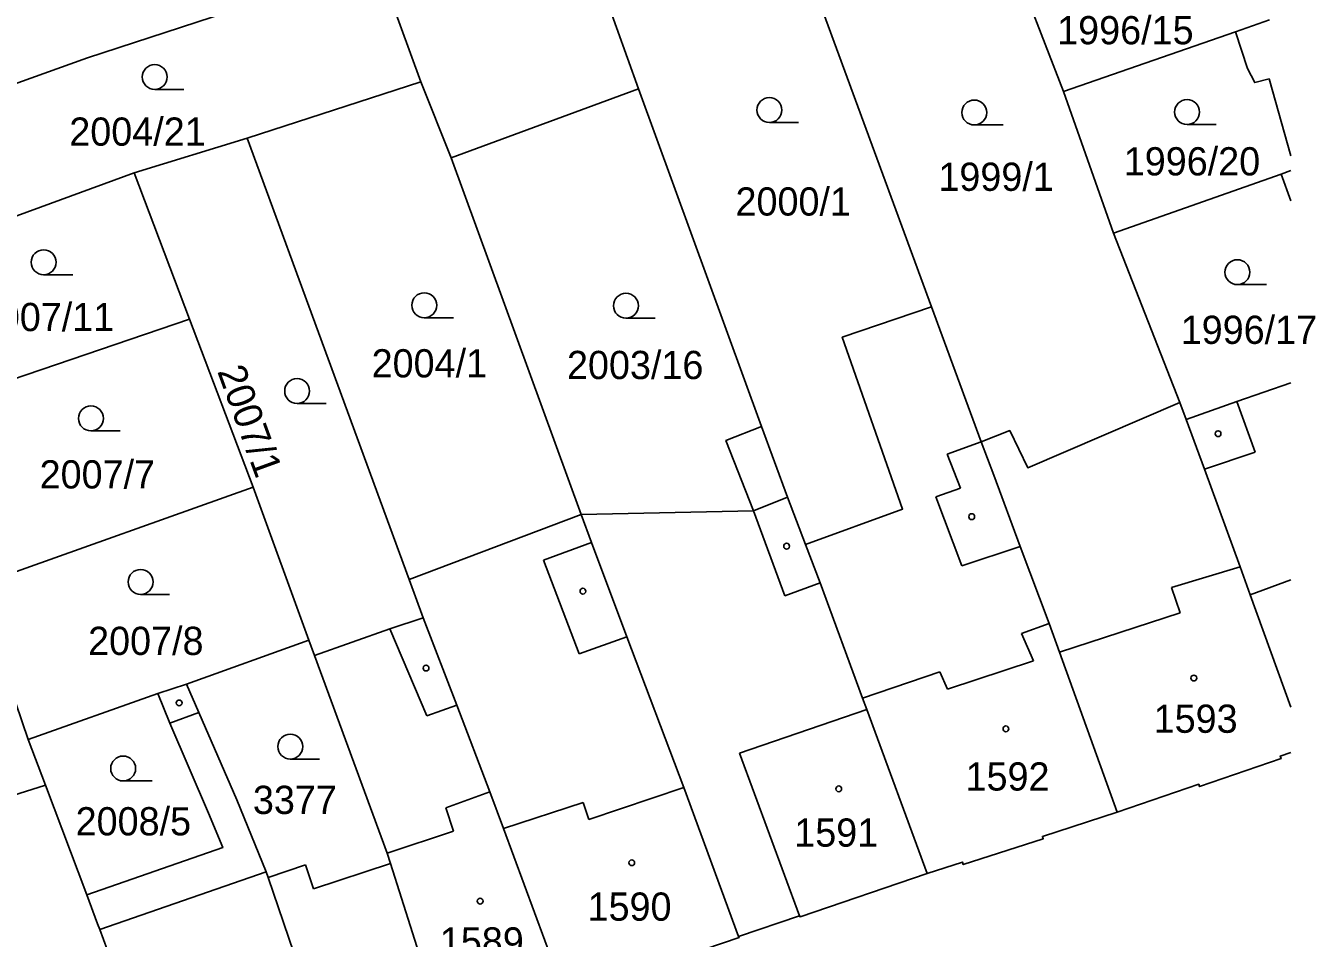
# Model space of a CAD drawing. Extents: x -564952 to -564307, y -1202373 to -1201847.
# Drawn here: x -564390.9 to -564313.2, y -1202270.6 to -1202215.7 of the extents above; entities that cross this region are included whole.
import ezdxf

# ---------------------------------------------------------------- set-up
doc = ezdxf.new("R2010")
doc.units = 0
for name, color, linetype in [('Hranice parcel', 7, 'Continuous'), ('Parcelní čísla', 7, 'Continuous'), ('Vnitřní kresba', 7, 'Continuous'), ('Značky budov', 7, 'Continuous'), ('Značky kultur', 7, 'Continuous')]:
    doc.layers.add(name, color=color, linetype=linetype)

msp = doc.modelspace()

# ---------------------------------------------------------------- linework, layer by layer
at = {"layer": 'Hranice parcel'}
for p, q in [((-564328.35, -1202219.63), (-564332.79, -1202208.17)), ((-564344.92, -1202209.13), (-564336.29, -1202232.6)), ((-564353.94, -1202219.47), (-564357.27, -1202210.21)), ((-564369.66, -1202211.88), (-564387.14, -1202217.59)), ((-564369.66, -1202211.88), (-564367.06, -1202219.05)), ((-564317.98, -1202216.02), (-564315.93, -1202215.31)), ((-564317.98, -1202216.02), (-564328.35, -1202219.63)), ((-564387.14, -1202217.59), (-564392.13, -1202219.38)), ((-564377.53, -1202222.44), (-564367.06, -1202219.05)), ((-564367.06, -1202219.05), (-564365.23, -1202223.62)), ((-564365.23, -1202223.62), (-564353.94, -1202219.47)), ((-564353.94, -1202219.47), (-564346.53, -1202239.8)), ((-564314.648, -1202223.506), (-564315.96, -1202218.87)), ((-564328.35, -1202219.63), (-564325.34, -1202228.16)), ((-564384.33, -1202224.53), (-564377.53, -1202222.44)), ((-564377.53, -1202222.44), (-564367.77, -1202249.02)), ((-564365.23, -1202223.62), (-564357.4, -1202245.11)), ((-564393.72, -1202227.96), (-564384.33, -1202224.53)), ((-564384.33, -1202224.53), (-564381, -1202233.34)), ((-564315.23, -1202224.6), (-564325.34, -1202228.16)), ((-564315.23, -1202224.6), (-564314.648, -1202224.392)), ((-564314.648, -1202226.212), (-564315.23, -1202224.6)), ((-564325.34, -1202228.16), (-564321.35, -1202238.36)), ((-564336.29, -1202232.6), (-564333.3, -1202240.74)), ((-564381, -1202233.34), (-564398.34, -1202239.24)), ((-564377.17, -1202243.46), (-564381, -1202233.34)), ((-564321.35, -1202238.36), (-564320.95, -1202239.38)), ((-564393.89, -1202249.42), (-564377.17, -1202243.46)), ((-564377.17, -1202243.46), (-564373.81, -1202252.67)), ((-564357.4, -1202245.11), (-564367.77, -1202249.02)), ((-564367.77, -1202249.02), (-564366.92, -1202251.33)), ((-564373.81, -1202252.67), (-564381.17, -1202255.32)), ((-564373.47, -1202253.61), (-564373.81, -1202252.67)), ((-564369.09, -1202265.51), (-564373.47, -1202253.61)), ((-564382.9, -1202255.9), (-564390.71, -1202258.66)), ((-564382.9, -1202255.9), (-564381.17, -1202255.32)), ((-564390.71, -1202258.66), (-564389.67, -1202261.41)), ((-564389.67, -1202261.41), (-564387.18, -1202268.03)), ((-564373.53, -1202267.65), (-564368.89, -1202266.13)), ((-564368.89, -1202266.13), (-564369.09, -1202265.51)), ((-564368.89, -1202266.13), (-564365.56, -1202276.57)), ((-564376.37, -1202266.64), (-564376.25, -1202266.98)), ((-564376.25, -1202266.98), (-564374.01, -1202266.22)), ((-564374.01, -1202266.22), (-564373.53, -1202267.65)), ((-564372.23, -1202278.84), (-564376.25, -1202266.98))]:
    msp.add_line(p, q, dxfattribs=at)
for points in [[(-564315.96, -1202218.87), (-564316.83, -1202219.09), (-564317.27, -1202218.23), (-564317.98, -1202216.02)], [(-564336.29, -1202232.6), (-564341.68, -1202234.43), (-564338.04, -1202244.78), (-564343.89, -1202246.92)], [(-564320.95, -1202239.38), (-564317.9, -1202238.31), (-564314.648, -1202237.168)], [(-564333.3, -1202240.74), (-564331.59, -1202240.05), (-564330.5, -1202242.29), (-564321.35, -1202238.36)], [(-564314.648, -1202256.715), (-564317.1, -1202249.94), (-564317.71, -1202248.27), (-564319.86, -1202242.37), (-564320.95, -1202239.38)], [(-564346.53, -1202239.8), (-564348.68, -1202240.65), (-564347.02, -1202244.89), (-564357.4, -1202245.11)], [(-564343.89, -1202246.92), (-564344.98, -1202244.07), (-564346.53, -1202239.8)], [(-564329.22, -1202251.67), (-564330.95, -1202247.03), (-564332.55, -1202242.74), (-564333.3, -1202240.74)], [(-564347.92, -1202270.53), (-564351.22, -1202261.56), (-564354.66, -1202252.48), (-564356.78, -1202246.8), (-564357.4, -1202245.11)], [(-564340.45, -1202256.18), (-564343.01, -1202249.22), (-564343.89, -1202246.92)], [(-564390.71, -1202258.66), (-564393.01, -1202251.97), (-564393.89, -1202249.42)], [(-564366.92, -1202251.33), (-564368.92, -1202251.99), (-564373.47, -1202253.61)], [(-564362.9, -1202261.82), (-564364.89, -1202256.6), (-564366.92, -1202251.33)], [(-564325.12, -1202263.05), (-564328.59, -1202253.41), (-564329.22, -1202251.67)], [(-564379.86, -1202263.1), (-564382.18, -1202257.68), (-564382.9, -1202255.9)], [(-564381.17, -1202255.32), (-564380.43, -1202257.03), (-564378.15, -1202262.3), (-564376.37, -1202266.64)], [(-564336.57, -1202266.74), (-564340.2, -1202256.86), (-564340.45, -1202256.18)], [(-564325.12, -1202263.05), (-564320.2, -1202261.36), (-564320.15, -1202261.5), (-564315.24, -1202259.81), (-564315.29, -1202259.66), (-564314.648, -1202259.44)], [(-564404.81, -1202265.7), (-564394.96, -1202262.25), (-564393.63, -1202262.65), (-564389.67, -1202261.41)], [(-564358.34, -1202274.15), (-564362.08, -1202264.03), (-564362.9, -1202261.82)], [(-564336.57, -1202266.74), (-564334.44, -1202266.05), (-564334.39, -1202266.2), (-564329.57, -1202264.64), (-564329.62, -1202264.5), (-564325.12, -1202263.05)], [(-564387.18, -1202268.03), (-564378.99, -1202265.17), (-564379.86, -1202263.1)], [(-564347.92, -1202270.53), (-564344.25, -1202269.28), (-564344.22, -1202269.35), (-564336.57, -1202266.74)], [(-564385.95, -1202271.31), (-564386.4, -1202270.12), (-564386.53, -1202269.77), (-564387.18, -1202268.03)], [(-564358.34, -1202274.15), (-564347.89, -1202270.6), (-564347.92, -1202270.53)]]:
    msp.add_lwpolyline(points, dxfattribs=at)
at = {"layer": 'Vnitřní kresba'}
for p, q in [((-564317.9, -1202238.31), (-564316.81, -1202241.36)), ((-564333.3, -1202240.74), (-564335.35, -1202241.47)), ((-564334.56, -1202243.53), (-564335.35, -1202241.47)), ((-564319.86, -1202242.37), (-564316.81, -1202241.36)), ((-564336.03, -1202244.05), (-564334.56, -1202243.53)), ((-564347.02, -1202244.89), (-564344.98, -1202244.07)), ((-564334.48, -1202248.21), (-564336.03, -1202244.05)), ((-564345.13, -1202250.01), (-564347.02, -1202244.89)), ((-564359.68, -1202247.86), (-564356.78, -1202246.8)), ((-564330.95, -1202247.03), (-564334.48, -1202248.21)), ((-564357.52, -1202253.5), (-564359.68, -1202247.86)), ((-564317.71, -1202248.27), (-564321.84, -1202249.51)), ((-564317.1, -1202249.94), (-564314.648, -1202249.043)), ((-564345.13, -1202250.01), (-564343.01, -1202249.22)), ((-564321.84, -1202249.51), (-564321.32, -1202251.03)), ((-564321.32, -1202251.03), (-564328.59, -1202253.41)), ((-564368.92, -1202251.99), (-564366.7, -1202257.24)), ((-564329.22, -1202251.67), (-564330.87, -1202252.28)), ((-564354.66, -1202252.48), (-564357.52, -1202253.5)), ((-564330.87, -1202252.28), (-564330.15, -1202253.92)), ((-564330.15, -1202253.92), (-564335.34, -1202255.63)), ((-564340.45, -1202256.18), (-564335.8, -1202254.59)), ((-564335.8, -1202254.59), (-564335.34, -1202255.63)), ((-564366.7, -1202257.24), (-564364.89, -1202256.6)), ((-564382.18, -1202257.68), (-564380.43, -1202257.03)), ((-564347.87, -1202259.48), (-564340.2, -1202256.86)), ((-564344.25, -1202269.28), (-564347.87, -1202259.48)), ((-564365.56, -1202262.79), (-564362.9, -1202261.82)), ((-564351.22, -1202261.56), (-564356.94, -1202263.49)), ((-564365.1, -1202264.19), (-564365.56, -1202262.79)), ((-564357.29, -1202262.46), (-564362.08, -1202264.03)), ((-564356.94, -1202263.49), (-564357.29, -1202262.46)), ((-564369.09, -1202265.51), (-564365.1, -1202264.19)), ((-564386.4, -1202270.12), (-564376.37, -1202266.64))]:
    msp.add_line(p, q, dxfattribs=at)
at = {"layer": 'Značky budov'}
for centre in [(-564319.037, -1202240.239), (-564333.877, -1202245.239), (-564345.027, -1202247.019), (-564357.297, -1202249.729), (-564366.747, -1202254.359), (-564320.497, -1202254.959), (-564381.617, -1202256.459), (-564331.817, -1202258.019), (-564341.887, -1202261.639), (-564354.357, -1202266.089), (-564363.487, -1202268.399)]:
    msp.add_circle(centre, 0.175, dxfattribs=at)
at = {"layer": 'Značky kultur'}
for p, q in [((-564383.093, -1202219.5), (-564381.343, -1202219.5)), ((-564346.063, -1202221.49), (-564344.313, -1202221.49)), ((-564333.723, -1202221.64), (-564331.973, -1202221.64)), ((-564320.903, -1202221.61), (-564319.153, -1202221.61)), ((-564389.783, -1202230.66), (-564388.033, -1202230.66)), ((-564317.873, -1202231.26), (-564316.123, -1202231.26)), ((-564366.853, -1202233.25), (-564365.103, -1202233.25)), ((-564354.703, -1202233.28), (-564352.953, -1202233.28)), ((-564374.513, -1202238.42), (-564372.763, -1202238.42)), ((-564386.933, -1202240.07), (-564385.183, -1202240.07)), ((-564383.943, -1202249.92), (-564382.193, -1202249.92)), ((-564374.923, -1202259.84), (-564373.173, -1202259.84)), ((-564384.993, -1202261.16), (-564383.243, -1202261.16))]:
    msp.add_line(p, q, dxfattribs=at)
for centre in [(-564383.093, -1202218.75), (-564346.063, -1202220.74), (-564333.723, -1202220.89), (-564320.903, -1202220.86), (-564389.783, -1202229.91), (-564317.873, -1202230.51), (-564366.853, -1202232.5), (-564354.703, -1202232.53), (-564374.513, -1202237.67), (-564386.933, -1202239.32), (-564383.943, -1202249.17), (-564374.923, -1202259.09), (-564384.993, -1202260.41)]:
    msp.add_circle(centre, 0.75, dxfattribs=at)

# ---------------------------------------------------------------- texts
at = {"layer": 'Parcelní čísla'}
for s, p in [('1996/15', (-564328.728, -1202216.78)), ('2004/21', (-564388.238, -1202222.89)), ('1996/20', (-564324.718, -1202224.68)), ('1999/1', (-564335.885, -1202225.61)), ('2000/1', (-564348.105, -1202227.1)), ('2007/11', (-564393.748, -1202234.06)), ('1996/17', (-564321.288, -1202234.83)), ('2004/1', (-564370.025, -1202236.85)), ('2003/16', (-564358.258, -1202236.95)), ('2007/7', (-564390.025, -1202243.54)), ('2007/8', (-564387.105, -1202253.57)), ('1593', (-564322.917, -1202258.26)), ('1592', (-564334.247, -1202261.74)), ('3377', (-564377.177, -1202263.15)), ('2008/5', (-564387.855, -1202264.44)), ('1591', (-564344.567, -1202265.12)), ('1590', (-564357.017, -1202269.58)), ('1589', (-564365.917, -1202271.68))]:
    msp.add_text(s, height=1.7, dxfattribs=at).set_placement(p)
msp.add_text('2007/1', height=1.7, rotation=290, dxfattribs=at).set_placement((-564379.339, -1202236.474))

doc.saveas('drawing.dxf')
